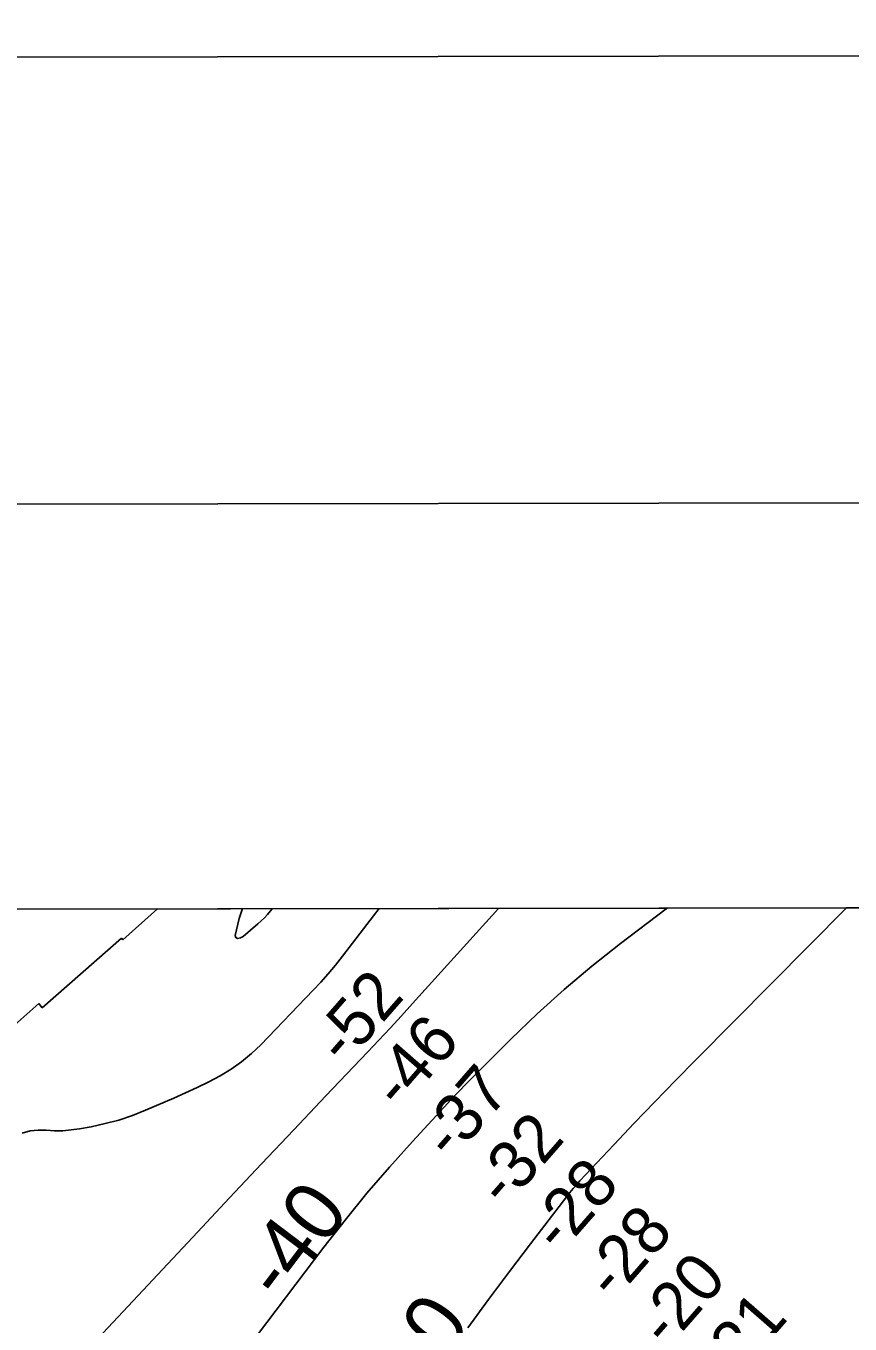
# Model space of a CAD drawing. Extents: x 3324125 to 3362000, y 600753 to 626151.
# Drawn here: x 3336321 to 3337474, y 623752 to 625567 of the extents above; entities that cross this region are included whole.
import ezdxf

# ---------------------------------------------------------------- set-up
doc = ezdxf.new("R2010")
doc.units = 0
for name, color, linetype in [('G-ANNO-NPLT', 7, 'Continuous'), ('V-ANNO-SYMB', 7, 'Continuous'), ('V-GRID-FRAM', 7, 'Continuous'), ('V-RIVR-RANG', 7, 'Continuous'), ('V-RRAP-RVMT', 7, 'Continuous'), ('V-TOPO-DPTH', 7, 'Continuous'), ('V-TOPO-MAJR', 7, 'Continuous'), ('V-TOPO-MINR', 7, 'Continuous'), ('V-TOPO-MINR-IDEN', 7, 'Continuous')]:
    doc.layers.add(name, color=color, linetype=linetype)

msp = doc.modelspace()

# ---------------------------------------------------------------- linework, layer by layer
at = {"layer": 'G-ANNO-NPLT'}
msp.add_lwpolyline([(3324750.5, 601336.7), (3361417.2, 601400.7), (3361375, 625567.3), (3324708.4, 625503.3)], close=True, dxfattribs=at)
at = {"layer": 'V-ANNO-SYMB'}
msp.add_lwpolyline([(3327499.6, 601966.6), (3360582.7, 602024.3), (3360542.7, 624940.8), (3327459.6, 624883.1), (3327499.6, 601966.6)], dxfattribs=at)
at = {"layer": 'V-GRID-FRAM'}
msp.add_lwpolyline([(3328210, 624318.2), (3328233.8, 606134.5), (3359834, 606189.7), (3359794.3, 624373.3), (3328210, 624318.2)], dxfattribs=at)
at = {"layer": 'V-RRAP-RVMT'}
for p, q in [((3336505, 624332.7), (3335752.8, 624331.3)), ((3336456.6, 624289.3), (3336505, 624332.7)), ((3336343.7, 624194.6), (3336454.5, 624291.6)), ((3336454.5, 624291.6), (3336456.6, 624289.3)), ((3336228.6, 624102.8), (3336338.7, 624200.4)), ((3336338.7, 624200.4), (3336343.7, 624194.6))]:
    msp.add_line(p, q, dxfattribs=at)
at = {"layer": 'V-TOPO-DPTH'}
for points in [[(3335154.4, 623578.2), (3335781.7, 624147.4), (3335802.7, 624167.5), (3335823.7, 624187.6), (3335832.4, 624196), (3335849.2, 624211.7), (3335866.3, 624227.1), (3335883.9, 624241.9), (3335901.8, 624256.4), (3335995.9, 624331.8), (3337217.7, 624333.9)], [(3336631.7, 623719.8), (3336737.5, 623859.5), (3336767.2, 623897.6), (3336797.7, 623935.1), (3336829.2, 623971.7), (3336861.5, 624007.6), (3336911, 624061.2), (3336919.1, 624069.9), (3336927.3, 624078.5), (3336935.6, 624087), (3336944, 624095.4), (3336999.2, 624150.6), (3337035.9, 624185.9), (3337073.6, 624220), (3337112.5, 624252.7), (3337152.4, 624284.3), (3337216.4, 624332.9), (3337217.7, 624333.9), (3337468.5, 624334.3)], [(3337217.7, 624333.9), (3337216.4, 624332.9), (3337152.4, 624284.3), (3337112.5, 624252.7), (3337073.6, 624220), (3337035.9, 624185.9), (3336999.2, 624150.6), (3336944, 624095.4), (3336935.6, 624087), (3336927.3, 624078.5), (3336919.1, 624069.9), (3336911, 624061.2), (3336861.5, 624007.6), (3336829.2, 623971.7), (3336797.7, 623935.1), (3336767.2, 623897.6), (3336737.5, 623859.5), (3336631.7, 623719.8)], [(3338370.1, 624335.9), (3337468.5, 624334.3), (3337258.8, 624122.6), (3337229.6, 624092.9), (3337200.6, 624063.1), (3337171.8, 624033), (3337143.1, 624002.7), (3337095.8, 623952.4), (3337091, 623947.1), (3337086.3, 623941.8), (3337081.8, 623936.3), (3337077.4, 623930.7), (3337026.6, 623864.4), (3336997.1, 623825.5), (3336967.9, 623786.3), (3336939.1, 623746.8)], [(3337468.5, 624334.3), (3337258.8, 624122.6), (3337229.6, 624092.9), (3337200.6, 624063.1), (3337171.8, 624033), (3337143.1, 624002.7), (3337095.8, 623952.4), (3337091, 623947.1), (3337086.3, 623941.8), (3337081.8, 623936.3), (3337077.4, 623930.7), (3337026.6, 623864.4), (3336997.1, 623825.5), (3336967.9, 623786.3), (3336939.1, 623746.8)]]:
    msp.add_lwpolyline(points, dxfattribs=at)
at = {"layer": 'V-TOPO-MAJR'}
msp.add_lwpolyline([(3336366.2, 623673.2), (3336560.7, 623880.8), (3336605.5, 623928.5), (3336650.4, 623976.1), (3336695.4, 624023.6), (3336740.4, 624071.1), (3336798.8, 624132.4), (3336814.7, 624149.2), (3336830.5, 624166.1), (3336846.1, 624183.1), (3336861.7, 624200.2), (3336982, 624333.5)], dxfattribs=at)
at = {"layer": 'V-TOPO-MINR'}
for points in [[(3336315.8, 624019.1), (3336326.6, 624022.2), (3336337.8, 624023.3), (3336349.3, 624023.2), (3336360.9, 624022.6), (3336372.5, 624022.6), (3336384, 624023.6), (3336395.6, 624025.2), (3336412, 624028.2), (3336431.5, 624032.4), (3336450.8, 624037.4), (3336469.7, 624043.8), (3336488.3, 624051.1), (3336527.6, 624068), (3336544, 624075.3), (3336560.4, 624083), (3336576.5, 624091), (3336592.5, 624099.4), (3336607.9, 624108.7), (3336622.6, 624118.8), (3336636.2, 624130.3), (3336649.3, 624142.6), (3336722.6, 624218.9), (3336733.3, 624230.4), (3336743.7, 624242.1), (3336753.8, 624254.1), (3336763.6, 624266.4), (3336807.2, 624322.9), (3336815, 624333.2)], [(3336623.7, 624332.9), (3336623.3, 624332.1), (3336619.1, 624319.5), (3336613.7, 624295.4), (3336614.4, 624292.6), (3336617, 624291.4), (3336621, 624292.1), (3336622.8, 624293), (3336624.5, 624294.1), (3336645.4, 624311.6), (3336650.1, 624315.8), (3336654.6, 624320.3), (3336658.8, 624325), (3336662.8, 624329.9), (3336665.1, 624332.9)], [(3336631.7, 623719.8), (3336737.5, 623859.5), (3336767.2, 623897.6), (3336797.7, 623935.1), (3336829.2, 623971.7), (3336861.5, 624007.6), (3336911, 624061.2), (3336919.1, 624069.9), (3336927.3, 624078.5), (3336935.6, 624087), (3336944, 624095.4), (3336999.2, 624150.6), (3337035.9, 624185.9), (3337073.6, 624220), (3337112.5, 624252.7), (3337152.4, 624284.3), (3337216.4, 624332.9), (3337217.7, 624333.9)], [(3336939.1, 623746.8), (3336967.9, 623786.3), (3336997.1, 623825.5), (3337026.6, 623864.4), (3337077.4, 623930.7), (3337081.8, 623936.3), (3337086.3, 623941.8), (3337091, 623947.1), (3337095.8, 623952.4), (3337143.1, 624002.7), (3337171.8, 624033), (3337200.6, 624063.1), (3337229.6, 624092.9), (3337258.8, 624122.6), (3337468.5, 624334.3)]]:
    msp.add_lwpolyline(points, dxfattribs=at)

# ---------------------------------------------------------------- texts
at = {"layer": 'V-RIVR-RANG'}
for s, p in [('-52', (3336766.6, 624111.7)), ('-46', (3336844.9, 624049.3)), ('-37', (3336915.9, 623978.6)), ('-32', (3336991.1, 623912.7)), ('-28', (3337068.1, 623848.8)), ('-28', (3337143.3, 623782.9)), ('-20', (3337218.3, 623716.7)), ('-21', (3337303.2, 623662))]:
    msp.add_text(s, height=67, rotation=48.9012, dxfattribs=at).set_placement(p)
at = {"layer": 'V-TOPO-MINR-IDEN'}
for s, rotation, p in [('-40', 52.8684, (3336678.3, 623781.4)), ('-30', 54.7057, (3336851.4, 623623.3))]:
    msp.add_text(s, height=83, rotation=rotation, dxfattribs=at).set_placement(p)

doc.saveas('drawing.dxf')
